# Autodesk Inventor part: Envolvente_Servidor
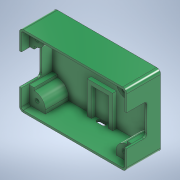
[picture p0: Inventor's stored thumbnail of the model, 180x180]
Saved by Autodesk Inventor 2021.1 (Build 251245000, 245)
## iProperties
Created: 2021-06
Part Number: Envolvente_Servidor
Material: Genérico
Document SubType Name: Modeling
Designer: Ricardo
Density: 1 g/cm^3
Appearance: Valor por defecto
Author: Ricardo
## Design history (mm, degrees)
sketch "Boceto1"
  geometry: L1 (-50, -32.5)-(50, -32.5); L2 (50, -32.5)-(50, 32.5); L3 (50, 32.5)-(-50, 32.5); L4 (-50, 32.5)-(-50, -32.5); L5 (-50, -32.5)-(50, 32.5); L6 (50, -32.5)-(-50, 32.5); L7 (-51, 33.5)-(51, 33.5); L8 (51, 33.5)-(51, -33.5); L9 (51, -33.5)-(-51, -33.5); L10 (-51, -33.5)-(-51, 33.5); L11 (53, 35.5)-(-53, 35.5); L12 (-53, 35.5)-(-53, -35.5); L13 (-53, -35.5)-(53, -35.5); L14 (53, -35.5)-(53, 35.5); 1 further point
  constraints: 28 end point, 6 parallel, 3 perpendicular, 2 midpoint, 1 horizontal, 6 other
  dimensions: "d0" = 100 distance of L3.end L2.end; "d1" = 65 distance of L2.end L1.end; "d2" = 1 distance between parallel lines of L3 L7; "d3" = 2 distance between parallel lines of L7 L11
extrude "Extrusión1" new body sketch "Boceto1" distance "d4" = 3; taper "d5" = 0 deg
extrude "Extrusión2" join sketch "Boceto1" distance "d6" = 30.6; taper "d7" = 0 deg
sketch "Boceto3"
  geometry: L1 (-43, -26.25)-(43, -26.25); L2 (43, -26.25)-(43, 26.25); L3 (43, 26.25)-(-43, 26.25); L4 (-43, 26.25)-(-43, -26.25); L5 (-43, -26.25)-(43, 26.25); L6 (43, -26.25)-(-43, 26.25); L7 (-51, -33.5)-(-51, 33.5) reference; L8 (-35, 19)-(-51, 19); L9 (-51, 19)-(-51, 33.5); L10 (-51, 33.5)-(-35, 33.5); L11 (-35, 33.5)-(-35, 19); L12 (-35, 19)-(-51, 33.5); L13 (-51, 19)-(-35, 33.5); L14 (-35, -19)-(-51, -19); L15 (-51, -19)-(-51, -33.5); L16 (-51, -33.5)-(-35, -33.5); L17 (-35, -33.5)-(-35, -19); L18 (-35, -19)-(-51, -33.5); L19 (-51, -19)-(-35, -33.5); L20 (51, -33.5)-(-51, -33.5) reference; L21 (35, -19)-(51, -19); L22 (51, -19)-(51, -33.5); L23 (51, -33.5)-(35, -33.5); L24 (35, -33.5)-(35, -19); L25 (35, -19)-(51, -33.5); L26 (51, -19)-(35, -33.5); L27 (35, 19)-(51, 19); L28 (51, 19)-(51, 33.5); L29 (51, 33.5)-(35, 33.5); L30 (35, 33.5)-(35, 19); L31 (35, 19)-(51, 33.5); L32 (51, 19)-(35, 33.5); C1 r 2 at (43, 26.25); C2 r 2 at (43, -26.25); C3 r 2 at (-43, -26.25); C4 r 2 at (-43, 26.25); 4 further points
  constraints: 60 end point, 10 midpoint, 10 parallel, 5 horizontal, 5 perpendicular, 4 centre point, 4 coincident, 2 point on line
  dimensions: "d8" = 86 distance of L3.end L2.end; "d9" = 52.5 distance of L2.end L1.end; "d10" = 4 diameter of C1; "d11" = 4 diameter of C2; "d12" = 4 diameter of C3; "d13" = 4 diameter of C4
extrude "Extrusión3" join sketch "Boceto3" distance "d14" = 23; taper "d15" = 0 deg
sketch "Boceto2"
  geometry: L1 (33.6, 71)-(0, 71) reference; L2 (0, 0)-(0, 71) reference; L3 (0, 0)-(33.6, 0) reference; L4 (33.6, 71)-(33.6, 0) reference; L5 (0, 0)-(0, 71) reference; L6 (33.6, 71)-(0, 0); L7 (0, 0)-(33.6, 0) reference; L8 (33.6, 0)-(0, 71); L9 (3, 54.5)-(3, 16.5) reference; L10 (26, 50.9)-(13.5, 50.9); L11 (13.5, 50.9)-(13.5, 20.1); L12 (13.5, 20.1)-(26, 20.1); L13 (26, 20.1)-(26, 50.9); L14 (26, 50.9)-(13.5, 20.1); L15 (13.5, 50.9)-(26, 20.1); L16 (0, 35.5)-(33.6, 35.5); L17 (33.6, 2)-(33.6, 69) reference; 3 further points
  constraints: 18 end point, 5 midpoint, 2 parallel, 1 horizontal, 1 perpendicular, 1 point on line
  dimensions: "d16" = 12.5 distance of L12.end L11.end; "d17" = 30.8 distance of L11.end L10.end; "d18" = 10.5 distance between parallel lines of L11 L9
extrude "Extrusión4" cut sketch "Boceto2" extent not by distance; stored distance "d19" = 0; taper "d20" = 0 deg
fillet "Empalme1" dims "d21" = 11
sketch "Boceto4"
  geometry: L1 (20.1, 18.1)-(20.1, 48.9) reference; L2 (20.1, 48.9)-(7.6, 48.9) reference; L3 (7.6, 48.9)-(7.6, 18.1) reference; L4 (7.6, 18.1)-(20.1, 18.1) reference; L5 (30.6, 49.9)-(7.6, 49.9); L6 (7.6, 17.1)-(30.6, 17.1); L7 (30.6, 52.5)-(30.6, 14.5) reference; L8 (7.6, 18.1)-(7.6, 48.9) reference; L9 (7.6, 48.9)-(7.6, 49.9); L10 (7.6, 18.1)-(7.6, 17.1); L11 (30.6, 17.1)-(7.6, 17.1); L12 (7.6, 17.1)-(7.6, 14.5); L13 (7.6, 14.5)-(30.6, 14.5); L14 (30.6, 14.5)-(30.6, 17.1); L15 (30.6, 49.9)-(7.6, 49.9); L16 (7.6, 49.9)-(7.6, 52.5); L17 (7.6, 52.5)-(30.6, 52.5); L18 (30.6, 52.5)-(30.6, 49.9); 3 further points
  constraints: 24 end point, 5 parallel, 3 point on line, 2 collinear, 2 perpendicular
  dimensions: "d22" = 1 distance between parallel lines of L4 L6
extrude "Extrusión5" join sketch "Boceto4" distance "d23" = 5; taper "d24" = 0 deg
mirror "Simetría1"
sketch "Boceto5"
  geometry: L1 (51, 16.4)-(46, 16.4) reference; L2 (46, 16.4)-(46, 19) reference; L3 (35, 30)-(35, 33.5) reference; L4 (35, 33.5)-(-35, 33.5) reference; L5 (-35, 33.5)-(-35, 30) reference; L6 (-46, 19)-(-46, 16.4) reference; L7 (-46, 16.4)-(-51, 16.4) reference; L8 (-51, 16.4)-(-51, -16.4) reference; L9 (-51, -16.4)-(-46, -16.4) reference; L10 (-46, -16.4)-(-46, -19) reference; L11 (-35, -30)-(-35, -33.5) reference; L12 (-35, -33.5)-(35, -33.5) reference; L13 (35, -33.5)-(35, -30) reference; L14 (46, -19)-(46, -16.4) reference; L15 (46, -16.4)-(51, -16.4) reference; L16 (51, -16.4)-(51, 16.4) reference; L17 (-35, -33.5)-(35, -33.5) reference; L18 (0, -33.5)-(0, 33.5); L19 (35, 33.5)-(-35, 33.5) reference; L20 (-8.5, -5.5)-(8.5, -5.5); L21 (8.5, -5.5)-(8.5, -33.5); L22 (8.5, -33.5)-(-8.5, -33.5); L23 (-8.5, -33.5)-(-8.5, -5.5); L24 (-8.5, -5.5)-(8.5, -33.5); L25 (8.5, -5.5)-(-8.5, -33.5); L26 (51, -33.5)-(-51, -33.5) reference; L27 (-12.5, -1.5)-(12.5, -1.5); L28 (12.5, -1.5)-(12.5, -33.5); L29 (-12.5, -33.5)-(-12.5, -1.5); A1 r 11 centre (46, 30) between (35, 30) and (46, 19) reference; A2 r 11 centre (-46, 30) between (-46, 19) and (-35, 30) reference; A3 r 11 centre (-46, -30) between (-35, -30) and (-46, -19) reference; A4 r 11 centre (46, -30) between (46, -19) and (35, -30) reference; 7 further points
  constraints: 20 end point, 6 midpoint, 3 parallel, 3 point on line, 2 perpendicular, 1 horizontal
  dimensions: "d25" = 17 distance of L21.end L22.end; "d26" = 28 distance of L20.end L21.end; "d27" = 4 distance between parallel lines of L23 L29
extrude "Extrusión6" join sketch "Boceto5" distance "d28" = 4; taper "d29" = 0 deg
sketch "Boceto6"
  geometry: L1 (44.5, 3)-(61.5, 3) reference; L2 (45.378, 5)-(59.809, 5); L3 (53, 3)-(53, 8.326); L4 (48, 5)-(58, 5); L5 (48, 2)-(58, 2); L6 (58, 8)-(48, 8); L7 (50.5, 3.6)-(55.5, 3.6); L8 (55.5, 7.6)-(50.5, 7.6); L9 (50.5, 5.6)-(55.5, 5.6); A1 r 3 centre (48, 5) between (48, 8) and (48, 2); A2 r 3 centre (58, 5) between (58, 2) and (58, 8); A3 r 2 centre (50.5, 5.6) between (50.5, 7.6) and (50.5, 3.6); A4 r 2 centre (55.5, 5.6) between (55.5, 3.6) and (55.5, 7.6); 3 further points
  constraints: 20 end point, 8 point on circle, 8 tangent, 4 centre point, 4 point on line, 2 horizontal, 2 midpoint, 2 parallel, 1 vertical
  dimensions: "d30" = 2 distance between parallel lines of L1 L2; "d31" = 5 distance of point (53, 5) L4.end; "d32" = 6 diameter of A2; "d52" = 2.5 distance of point (53, 5.6) L9.end; "d53" = 4 diameter of A4; "d56" = 0.6 distance between parallel lines of L9 L4
extrude "Extrusión7" cut sketch "Boceto6" stored distance "d33" = 0; taper "d34" = 0 deg
fillet "Empalme2" dims "d35" = 4
sketch "Boceto7"
  geometry: L1 (-43, 26.25)-(13.26, 26.25); L2 (-27.444, 26.25)-(-27.444, 22.585); L3 (13.26, 26.25)-(13.26, 19); C1 r 2 at (-43, 26.25) reference; C2 r 2 at (-43, 26.25) reference; C3 r 4 at (-27.444, 22.585); C4 r 2.5 at (13.26, 19); 1 further point
  constraints: 6 end point, 2 centre point, 2 coincident, 2 vertical, 1 horizontal, 1 point on line
  dimensions: "d36" = 15.556 distance of C1.centre L2.start; "d37" = 3.665 distance of L2.start L2.end; "d38" = 8 diameter of C3; "d41" = 7.25 distance of L1.end L3.end; "d42" = 56.26 distance from line of C1.centre L3; "d43" = 5 diameter of C4
extrude "Extrusión8" cut sketch "Boceto7" distance "d39" = 10; taper "d40" = 0 deg
sketch "Boceto8"
  geometry: L1 (20.1, 16.1)-(7.6, 16.1) reference; L2 (7.6, 16.1)-(7.6, 46.9) reference; L3 (7.6, 46.9)-(20.1, 46.9) reference; L4 (20.1, 46.9)-(20.1, 16.1) reference; L5 (0, 63)-(33.6, 63) reference; L6 (0, 0)-(0, 63) reference; L7 (33.6, 0)-(0, 0) reference; L8 (33.6, 63)-(33.6, 0) reference; L9 (7.6, 46.9)-(7.6, 16.1) reference; L10 (7.6, 16.1)-(0, 16.1); L11 (0, 65)-(0, -2) reference; L12 (20.1, 46.9)-(7.6, 46.9) reference; L13 (7.6, 46.9)-(0, 46.9); 2 further points
  constraints: 4 end point, 2 perpendicular, 2 point on line
extrude "Extrusión9" cut sketch "Boceto8" extent not by distance; stored distance "d44" = 0; taper "d45" = 0 deg
sketch "Boceto9"
  geometry: L1 (-53, 21.997)-(53, 21.997); L2 (53, 21.997)-(53, -8.046); L3 (53, -8.046)-(-53, -8.046); L4 (-53, -8.046)-(-53, 21.997); L5 (-53, 31.5)-(-53, -31.5) reference; L6 (53, -31.5)-(53, 31.5) reference; L7 (-49, -35.5)-(49, -35.5); L8 (-0.099, -15.348)-(-0.099, -16.765); L9 (-0.099, -16.765)-(-4.334, -16.765); L10 (-4.334, -16.765)-(-8.569, -16.765); L11 (-8.569, -16.765)-(-8.569, -15.348); L12 (-8.569, -15.348)-(-8.569, -13.93); L13 (-8.569, -13.93)-(-4.334, -13.93); L14 (-4.334, -13.93)-(-0.099, -13.93); L15 (-0.099, -13.93)-(-0.099, -15.348); L16 (3.961, -15.348)-(3.961, -16.765); L17 (3.961, -16.765)-(2.351, -16.765); L18 (2.351, -16.765)-(0.741, -16.765); L19 (0.741, -16.765)-(0.741, -15.348); L20 (0.741, -15.348)-(0.741, -13.93); L21 (0.741, -13.93)-(2.351, -13.93); L22 (2.351, -13.93)-(3.961, -13.93); L23 (3.961, -13.93)-(3.961, -15.348); L24 (8.021, -15.348)-(8.021, -16.765); L25 (8.021, -16.765)-(6.411, -16.765); L26 (6.411, -16.765)-(4.801, -16.765); L27 (4.801, -16.765)-(4.801, -15.348); L28 (4.801, -15.348)-(4.801, -13.93); L29 (4.801, -13.93)-(6.411, -13.93); L30 (6.411, -13.93)-(8.021, -13.93); L31 (8.021, -13.93)-(8.021, -15.348); L32 (-0.099, -18.988)-(-0.099, -20.405); L33 (-0.099, -20.405)-(-4.334, -20.405); L34 (-4.334, -20.405)-(-8.569, -20.405); L35 (-8.569, -20.405)-(-8.569, -18.988); L36 (-8.569, -18.988)-(-8.569, -17.57); L37 (-8.569, -17.57)-(-4.334, -17.57); L38 (-4.334, -17.57)-(-0.099, -17.57); L39 (-0.099, -17.57)-(-0.099, -18.988); L40 (3.961, -20.86)-(3.961, -24.15); L41 (3.961, -24.15)-(2.351, -24.15); L42 (2.351, -24.15)-(0.741, -24.15); L43 (0.741, -24.15)-(0.741, -20.86); L44 (0.741, -20.86)-(0.741, -17.57); L45 (0.741, -17.57)-(2.351, -17.57); L46 (2.351, -17.57)-(3.961, -17.57); L47 (3.961, -17.57)-(3.961, -20.86); L48 (8.021, -20.86)-(8.021, -24.15); L49 (8.021, -24.15)-(6.411, -24.15); L50 (6.411, -24.15)-(4.801, -24.15); L51 (4.801, -24.15)-(4.801, -20.86); L52 (4.801, -20.86)-(4.801, -17.57); L53 (4.801, -17.57)-(6.411, -17.57); L54 (6.411, -17.57)-(8.021, -17.57); L55 (8.021, -17.57)-(8.021, -20.86); L56 (-0.099, -22.698)-(-0.099, -24.15); L57 (-0.099, -24.15)-(-4.334, -24.15); L58 (-4.334, -24.15)-(-8.569, -24.15); L59 (-8.569, -24.15)-(-8.569, -22.698); L60 (-8.569, -22.698)-(-8.569, -21.245); L61 (-8.569, -21.245)-(-4.334, -21.245); L62 (-4.334, -21.245)-(-0.099, -21.245); L63 (-0.099, -21.245)-(-0.099, -22.698); A1 r 11.255 centre (-0.239, -19.215) between (-0.694, -7.969) and (-4.038, -8.62); A2 r 11.025 centre (-0.317, -18.998) between (-4.038, -8.62) and (-7.013, -10.239); A3 r 11.023 centre (-0.318, -18.997) between (-7.013, -10.239) and (-9.357, -12.686); A4 r 11.249 centre (-0.133, -19.126) between (-9.357, -12.686) and (-10.861, -15.741); A5 r 10.537 centre (-0.812, -18.911) between (-10.861, -15.741) and (-11.3, -17.894); A6 r 11.498 centre (0.144, -19.004) between (-11.3, -17.894) and (-11.297, -20.14); A7 r 11.48 centre (0.126, -19.006) between (-11.297, -20.14) and (-10.858, -22.341); A8 r 10.459 centre (-0.851, -19.303) between (-10.858, -22.341) and (-10.005, -24.36); A9 r 11.212 centre (-0.191, -18.938) between (-10.005, -24.36) and (-8.564, -26.396); A10 r 11.206 centre (-0.196, -18.942) between (-8.564, -26.396) and (-6.708, -28.062); A11 r 11.125 centre (-0.243, -19.009) between (-6.708, -28.062) and (-4.536, -29.271); A12 r 10.854 centre (-0.348, -19.259) between (-4.536, -29.271) and (-2.164, -29.959); A13 r 12.046 centre (-0.148, -18.083) between (-2.164, -29.959) and (-1.695, -30.029); A14 r 8.551 centre (-0.597, -21.549) between (-1.695, -30.029) and (-1.262, -30.074); A15 r 9.448 centre (-0.527, -20.655) between (-1.262, -30.074) and (-0.808, -30.099); A16 r 17.951 centre (-0.274, -12.156) between (-0.808, -30.099) and (-0.274, -30.107); A17 r 17.951 centre (-0.274, -12.156) between (-0.274, -30.107) and (0.26, -30.099); A18 r 9.448 centre (-0.021, -20.655) between (0.26, -30.099) and (0.714, -30.074); A19 r 8.551 centre (0.048, -21.549) between (0.714, -30.074) and (1.147, -30.029); A20 r 12.046 centre (-0.4, -18.083) between (1.147, -30.029) and (1.616, -29.959); A21 r 10.892 centre (-0.207, -19.221) between (1.616, -29.959) and (3.785, -29.355); A22 r 11.053 centre (-0.266, -19.071) between (3.785, -29.355) and (5.792, -28.316); A23 r 11.112 centre (-0.299, -19.022) between (5.792, -28.316) and (7.551, -26.887); A24 r 11.157 centre (-0.331, -18.99) between (7.551, -26.887) and (8.985, -25.13); A25 r 14.392 centre (-3.031, -17.209) between (8.985, -25.13) and (9.301, -24.629); A26 r 9.132 centre (1.476, -19.921) between (9.301, -24.629) and (9.56, -24.168); A27 r 8.9 centre (1.681, -20.029) between (9.56, -24.168) and (9.789, -23.699); A28 r 12.958 centre (-2.015, -18.356) between (9.789, -23.699) and (10.015, -23.17); A29 r 11.027 centre (-0.223, -19.073) between (10.015, -23.17) and (10.663, -20.831); A30 r 11.241 centre (-0.435, -19.039) between (10.663, -20.831) and (10.788, -18.394); A31 r 11.202 centre (-0.395, -19.037) between (10.788, -18.394) and (10.385, -15.992); A32 r 10.855 centre (-0.061, -18.942) between (10.385, -15.992) and (9.474, -13.755); A33 r 11.043 centre (-0.226, -19.032) between (9.474, -13.755) and (8.041, -11.712); A34 r 11.199 centre (-0.343, -19.136) between (8.041, -11.712) and (6.182, -10.034); A35 r 11.158 centre (-0.319, -19.102) between (6.182, -10.034) and (4, -8.814); A36 r 10.864 centre (-0.206, -18.832) between (4, -8.814) and (1.616, -8.121); A37 r 8.962 centre (0.113, -16.956) between (1.616, -8.121) and (1.074, -8.046); A38 r 14.998 centre (-0.534, -22.958) between (1.074, -8.046) and (0.455, -7.992); A39 r 14.839 centre (-0.524, -22.799) between (0.455, -7.992) and (-0.162, -7.964); A40 r 8.216 centre (-0.362, -16.178) between (-0.162, -7.964) and (-0.694, -7.969); 99 further points
  constraints: 114 end point, 80 point on circle, 40 centre point, 2 midpoint, 2 point on line, 2 other
extrude "Extrusión10" cut sketch "Boceto9" distance "d47" = 2; taper "d48" = 0 deg
fillet "Empalme3" dims "d49" = 2
fillet "Empalme4" dims "d50" = 3
node "Sólido1"
node "Contorno proyectado1"
node "Contorno proyectado2"
node "Contorno proyectado3"
